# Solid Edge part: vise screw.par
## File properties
Title: Vise Screw
Author: Abhinav Rai
Template: Normal.par
Last saved by: Cadcim
Revision: 6
Application: Solid Edge
Density: 0.0000078 kg/mm^3
Accuracy: 0.01
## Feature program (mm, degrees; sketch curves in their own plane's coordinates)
sketch for "unnamed RevolvedProtrusion 1" plane through (0, 0, 0) normal (0, -1, 0) x-axis (1, 0, 0)
  line (9.525, 77.2518) -> (9.525, 56.627)
  line (9.525, 56.627) -> (6.35, 56.627)
  line (6.35, 56.627) -> (6.35, 50.277)
  line (6.35, 50.277) -> (7.9375, 50.277)
  line (7.9375, 50.277) -> (7.9375, -49.7228)
  line (7.9375, -49.7228) -> (6.35, -49.7228)
  line (6.35, -49.7228) -> (6.35, -72.5828)
  line (6.35, -72.5828) -> (4.7625, -72.5828)
  line (4.7625, -72.5828) -> (4.7625, -75.1482)
  line (4.7625, -75.1482) -> (6.35, -75.1482)
  line (6.35, -75.1482) -> (6.35, -81.4982)
  line (6.35, -81.4982) -> (0, -81.4982)
  line (0, -81.4982) -> (0, 77.2518)
  line (0, 77.2518) -> (9.525, 77.2518)
revolve "unnamed RevolvedProtrusion 1" add finite 360 deg
sketch for "unnamed Hole 1" plane through (0, 0, 0) normal (0, -1, 0) x-axis (1, 0, 0)
  hole centre (0, 66.9394) bore radius 4.3688
hole "unnamed Hole 1" through
sketch for "unnamed Hole 2" plane through (0, 0, 0) normal (0, -1, 0) x-axis (1, 0, 0)
  hole centre (0, 66.9394) bore radius 4.3688
hole "unnamed Hole 2" through
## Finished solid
Body 1: solid body, 14 faces, 14 edges, 0 vertices.
  Faces by surface: cylinder 7, plane 7
  Edges by curve: circle 12, intersection 2
Bounding box of the edges (mm): 19.050 x 19.050 x 158.750, from (-9.525, -9.525, -81.4982) to (9.525, 9.525, 77.2518).
Cylindrical faces by radius (mm): R4.3688 x1, R4.7625 x1, R6.35 x3, R7.9375 x1, R9.525 x1
Planar faces by outward normal: +z 3, -z 4
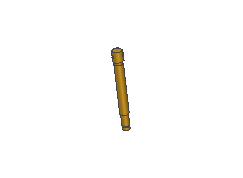
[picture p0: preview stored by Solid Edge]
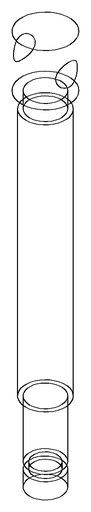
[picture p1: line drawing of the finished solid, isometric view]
